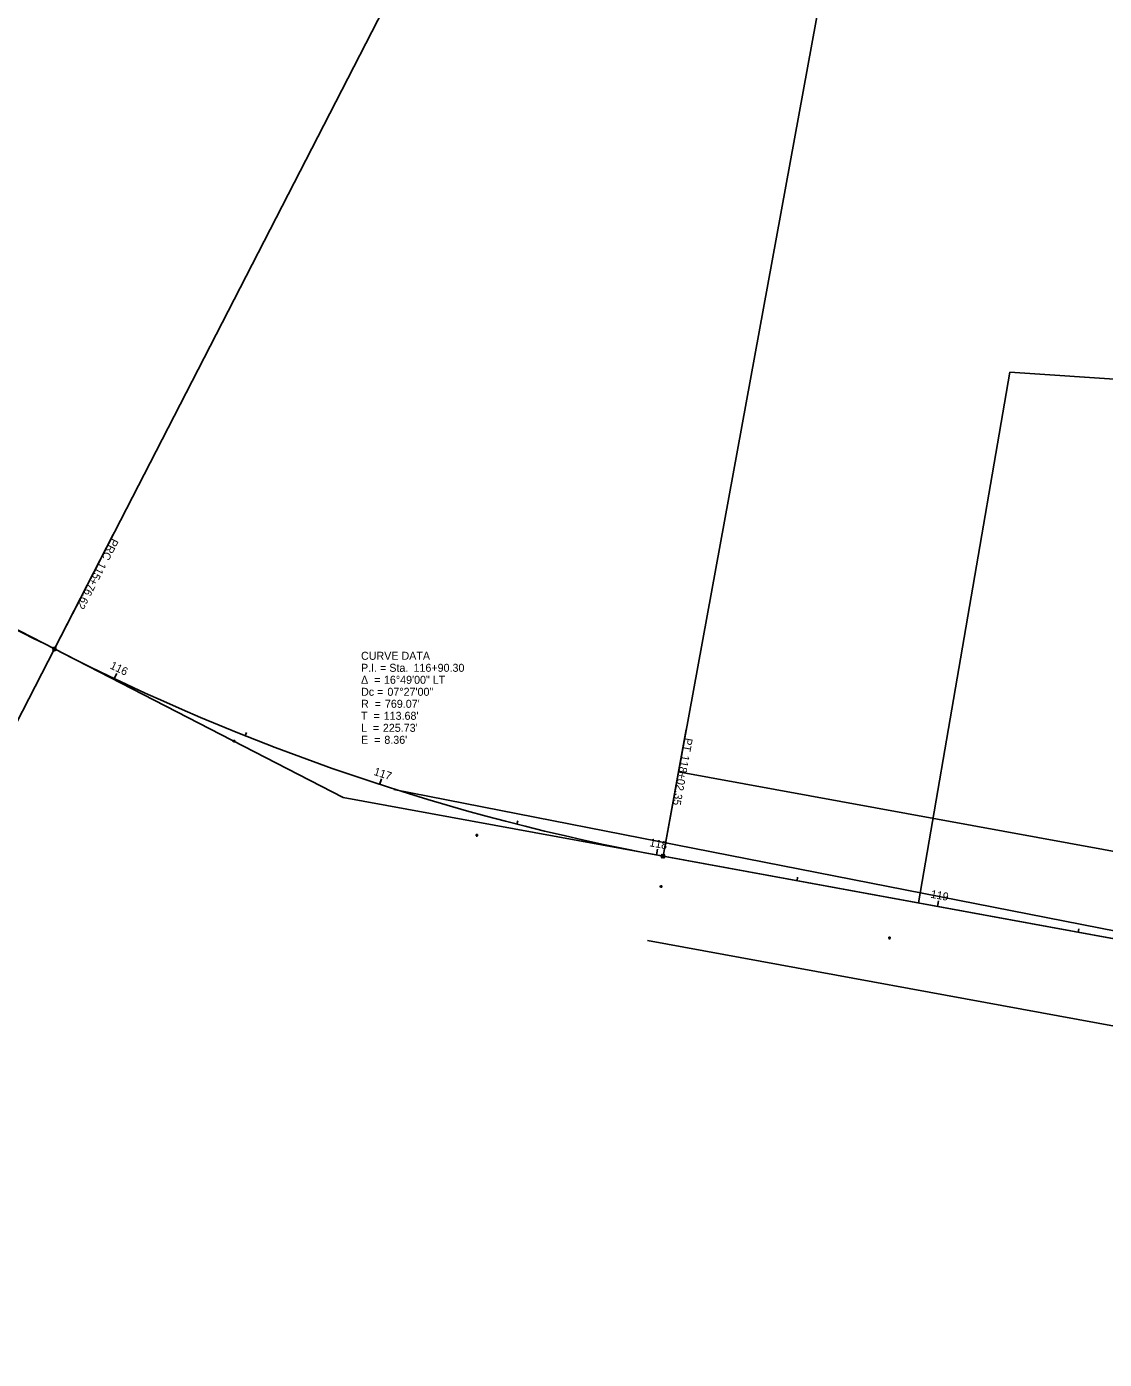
# Model space of a CAD drawing. Extents: x 2003596 to 2006933, y 570827 to 573780.
# Drawn here: x 2004322.4 to 2004699.4, y 572548.4 to 573014.7 of the extents above; entities that cross this region are included whole.
import ezdxf

# ---------------------------------------------------------------- set-up
doc = ezdxf.new("R2010")
doc.units = 0
for name, color, linetype in [('DV_X_Property_Line', 7, 'Continuous'), ('GE_X_Alignment', 7, 'Continuous'), ('GE_X_Alignment_1000_Cardinal_Points', 7, 'Continuous'), ('GE_X_Alignment_1000_Curve_Data', 7, 'Continuous'), ('GE_X_Alignment_100_Cardinal_Points', 7, 'Continuous'), ('GE_X_Alignment_100_Stations', 7, 'Continuous'), ('GE_X_Alignment_500_Cardinal_Points', 7, 'Continuous'), ('GE_X_Alignment_500_Stations', 7, 'Continuous'), ('RW_X_CL', 7, 'Continuous'), ('RW_X_Esmt_SH', 7, 'Continuous'), ('SC_Scratch1', 7, 'Continuous'), ('SC_Scratch8', 7, 'Continuous'), ('SV_X_Random_Point', 7, 'Continuous'), ('SV_X_Shot_Marker', 7, 'Continuous')]:
    doc.layers.add(name, color=color, linetype=linetype)

msp = doc.modelspace()

# ---------------------------------------------------------------- linework, layer by layer
at = {"layer": 'DV_X_Property_Line'}
for p, q in [((2004634.4, 572708.11), (2004666.28, 572893.76)), ((2004666.28, 572893.76), (2004864, 572880.82))]:
    msp.add_line(p, q, dxfattribs=at)
at = {"layer": 'GE_X_Alignment'}
msp.add_line((2004545, 572724.5), (2005031.48, 572635.32), dxfattribs=at)
for centre, radius, start, end in [((2003885.35, 571928), 977.08, 62.79264, 78.09264), ((2004683.7, 573480.96), 769.07, 242.79359, 259.61026)]:
    msp.add_arc(centre, radius, start, end, dxfattribs=at)
at = {"layer": 'GE_X_Alignment_1000_Cardinal_Points'}
for p, q in [((2004332.08, 572796.97), (2004352.66, 572837)), ((2004545, 572724.5), (2004553.12, 572768.76))]:
    msp.add_line(p, q, dxfattribs=at)
for centre in [(2004332.08, 572796.97), (2004545, 572724.5)]:
    msp.add_circle(centre, 0.6, dxfattribs=at)
at = {"layer": 'GE_X_Alignment_100_Cardinal_Points'}
for p, q in [((2004332.08, 572796.97), (2004352.66, 572837)), ((2004545, 572724.5), (2004553.12, 572768.76))]:
    msp.add_line(p, q, dxfattribs=at)
for centre in [(2004332.08, 572796.97), (2004545, 572724.5)]:
    msp.add_circle(centre, 0.6, dxfattribs=at)
at = {"layer": 'GE_X_Alignment_100_Stations'}
for p, q in [((2004353.04, 572786.6), (2004353.9, 572788.41)), ((2004398.85, 572766.59), (2004399.29, 572767.7)), ((2004445.86, 572749.59), (2004446.48, 572751.49)), ((2004493.88, 572735.68), (2004494.17, 572736.85)), ((2004542.7, 572724.92), (2004543.06, 572726.89)), ((2004591.88, 572715.91), (2004592.09, 572717.09)), ((2004641.06, 572706.89), (2004641.42, 572708.86)), ((2004690.24, 572697.87), (2004690.45, 572699.05))]:
    msp.add_line(p, q, dxfattribs=at)
at = {"layer": 'GE_X_Alignment_500_Cardinal_Points'}
for p, q in [((2004332.08, 572796.97), (2004352.66, 572837)), ((2004545, 572724.5), (2004553.12, 572768.76))]:
    msp.add_line(p, q, dxfattribs=at)
for centre in [(2004332.08, 572796.97), (2004545, 572724.5)]:
    msp.add_circle(centre, 0.6, dxfattribs=at)
at = {"layer": 'GE_X_Alignment_500_Stations'}
for p, q in [((2004353.04, 572786.6), (2004353.55, 572787.69)), ((2004445.86, 572749.59), (2004446.23, 572750.73)), ((2004542.7, 572724.92), (2004542.92, 572726.1)), ((2004641.06, 572706.89), (2004641.27, 572708.07))]:
    msp.add_line(p, q, dxfattribs=at)
at = {"layer": 'RW_X_CL'}
msp.add_line((2005031.48, 572635.32), (2004545, 572724.5), dxfattribs=at)
at = {"layer": 'RW_X_Esmt_SH'}
for p, q in [((2004550.41, 572754.01), (2005034.78, 572665.22)), ((2004539.59, 572694.99), (2005028.18, 572605.42))]:
    msp.add_line(p, q, dxfattribs=at)
at = {"layer": 'SC_Scratch1'}
for p, q in [((2004683.7, 573480.96), (2004332.08, 572796.97)), ((2004683.7, 573480.96), (2004545, 572724.5)), ((2004215.36, 572856.98), (2004332.08, 572796.97)), ((2003885.35, 571928), (2004332.08, 572796.97)), ((2004332.08, 572796.97), (2004433.11, 572745.04)), ((2004433.11, 572745.04), (2005031.48, 572635.32))]:
    msp.add_line(p, q, dxfattribs=at)
at = {"layer": 'SC_Scratch8'}
msp.add_line((2005021.66, 572635.7), (2004450.87, 572747.83), dxfattribs=at)
at = {"layer": 'SV_X_Random_Point'}
for p, q in [((2004331.42, 572796.31), (2004332.75, 572797.64)), ((2004331.42, 572797.64), (2004332.75, 572796.31)), ((2004544.34, 572723.83), (2004545.67, 572725.17)), ((2004544.34, 572725.17), (2004545.67, 572723.83))]:
    msp.add_line(p, q, dxfattribs=at)
at = {"layer": 'SV_X_Shot_Marker'}
for p, q in [((2004394.44, 572764.71), (2004395.44, 572764.71)), ((2004394.94, 572765.21), (2004394.94, 572764.21)), ((2004394.94, 572764.71), (2004394.94, 572764.71)), ((2004479.34, 572731.78), (2004480.34, 572731.78)), ((2004479.84, 572732.28), (2004479.84, 572731.28)), ((2004479.84, 572731.78), (2004479.84, 572731.78)), ((2004543.81, 572713.89), (2004544.81, 572713.89)), ((2004544.31, 572714.39), (2004544.31, 572713.39)), ((2004544.31, 572713.89), (2004544.31, 572713.89)), ((2004623.72, 572695.87), (2004624.72, 572695.87)), ((2004624.22, 572696.37), (2004624.22, 572695.37)), ((2004624.22, 572695.87), (2004624.22, 572695.87))]:
    msp.add_line(p, q, dxfattribs=at)

# ---------------------------------------------------------------- texts
at = {"layer": 'GE_X_Alignment_1000_Cardinal_Points'}
for s, rotation, p in [('PRC', 242.7936, (2004352.17, 572835.94)), ('115+76.62', 242.7936, (2004347.89, 572827.63)), ('PT', 259.6122, (2004552.66, 572766.02)), ('118+02.35', 259.6122, (2004551.57, 572760.04))]:
    msp.add_text(s, height=2.8, rotation=rotation, dxfattribs=at).set_placement(p)
at = {"layer": 'GE_X_Alignment_1000_Curve_Data'}
for s, p in [('CURVE DATA', (2004439.35, 572793.19)), ('P.I. = Sta. ', (2004439.35, 572788.99)), ('116+90.30', (2004457.71, 572788.99)), ('Δ  = ', (2004439.35, 572784.79)), ('16°49\'00" LT', (2004447.37, 572784.79)), ('Dc = ', (2004439.35, 572780.59)), ('07°27\'00"', (2004448.58, 572780.59)), ('R  = ', (2004439.35, 572776.39)), ("769.07'", (2004447.71, 572776.39)), ('T  = ', (2004439.35, 572772.19)), ('L  = ', (2004439.35, 572767.99)), ("225.73'", (2004446.99, 572767.99)), ("113.68'", (2004447.28, 572772.19)), ('E  = ', (2004439.35, 572763.79)), ("8.36'", (2004447.5, 572763.79))]:
    msp.add_text(s, height=2.8, dxfattribs=at).set_placement(p)
at = {"layer": 'GE_X_Alignment_100_Cardinal_Points'}
for s, rotation, p in [('PRC', 242.7936, (2004352.17, 572835.94)), ('115+76.62', 242.7936, (2004347.89, 572827.63)), ('PT', 259.6122, (2004552.66, 572766.02)), ('118+02.35', 259.6122, (2004551.57, 572760.04))]:
    msp.add_text(s, height=2.8, rotation=rotation, dxfattribs=at).set_placement(p)
at = {"layer": 'GE_X_Alignment_100_Stations'}
for s, rotation, p in [('116', 334.5354, (2004351.3, 572790.25)), ('117', 341.9854, (2004443.59, 572752.95)), ('118', 349.4354, (2004540.08, 572728)), ('119', 349.6122, (2004638.46, 572709.96))]:
    msp.add_text(s, height=2.8, rotation=rotation, dxfattribs=at).set_placement(p)
at = {"layer": 'GE_X_Alignment_500_Cardinal_Points'}
for s, rotation, p in [('PRC', 242.7936, (2004352.17, 572835.94)), ('115+76.62', 242.7936, (2004347.89, 572827.63)), ('PT', 259.6122, (2004552.66, 572766.02)), ('118+02.35', 259.6122, (2004551.57, 572760.04))]:
    msp.add_text(s, height=2.8, rotation=rotation, dxfattribs=at).set_placement(p)

doc.saveas('drawing.dxf')
